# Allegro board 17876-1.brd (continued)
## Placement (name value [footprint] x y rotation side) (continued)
NOREF#57  *  [unnamed]  4.72 13.84 180 bottom
NOREF#58  *  [unnamed]  126.58 2.01 180 bottom
NOREF#59  *  [unnamed]  150.69 1.28 180 bottom
NOREF#60  *  [unnamed]  167.46 98.3 180 bottom
PC4301  SC1U50V3KX-1-GP  [C603H36]  27.1 70 270 bottom
PC4302  SCD1U25V2KX-1-DL-GP  [C402H22]  25.91 70.05 90 top
PC4303  SCD01U50V2KX-1GP  [C402H22]  20.9 64.95 90 bottom
PC4304  SCD01U50V2KX-1DLGP  [C402H22]  20.9 60.99 90 bottom
PC4305  SCD01U50V2KX-1GP  [C402H22]  20.9 61.77 90 bottom
PC4306  SC10U25V5KX-DL-GP  [C805H58]  20.52 66.3 90 bottom
PC4401  SC10U25V5KX-DL-GP  [C805H58]  125.28 14.63 0 bottom
PC4402  SC2200P50V2KX-2DLGP  [C402H22]  139.62 37.82 180 bottom
PC4403  SC2200P50V2KX-2DLGP  [C402H22]  140.41 37.82 180 bottom
PC4404  SC1U10V2KX-1DLGP  [C402H22]  21.51 55.15 0 bottom
PC4405  SCD022U16V2KX-3GP  [C402H22]  142.51 36.27 0 bottom
PC4406  SC560P50V2KX-2DLGP  [C402H22]  142.32 34.11 0 bottom
PC4407  SC1KP50V2KX-1DLGP  [C402H22]  134.24 32.51 0 bottom
PC4408  SC1KP50V2KX-1DLGP  [C402H22]  134.24 30.94 180 bottom
PC4409  SC1KP50V2KX-1DLGP  [C402H22]  134.24 33.99 0 bottom
PC4410  SC10U25V5KX-DL-GP  [C805H58]  123.48 14.63 0 bottom
PC4411  SC10U25V5KX-DL-GP  [C805H58]  129.08 10.12 270 bottom
PC4418  SC10U25V5KX-DL-GP  [C805H58]  133.63 20.98 90 bottom
PC4419  SCD01U50V2KX-1DLGP  [C402H22]  135.84 36.86 90 bottom
PC4427  SC10U25V5KX-DL-GP  [C805H58]  133.63 22.89 90 bottom
PC4431  SCD22U25V3KX-DL-GP  [C603H36]  137.16 28.27 0 bottom
PC4433  SCD47U25V3KX-1-DL-GP  [C603H36]  22.15 43.74 0 bottom
PC4435  SC1U50V3KX-1-GP  [C603H36]  140.56 27.08 270 bottom
PC4436  SC10P50V2JN-4DLGP  [C402H22]  140.08 32.77 270 top
PC4438  SC10U25V5KX-DL-GP  [C805H58]  138.81 23.19 270 bottom
PC4445  SC1U10V2KX-1DLGP  [C402H22]  138.58 27.38 270 bottom
PC4446  SC1U10V2KX-1DLGP  [C402H22]  138.43 31.19 270 top
PC4452  SC10U25V5KX-DL-GP  [C805H58]  129.08 11.95 270 bottom
PC4453  SC10U25V5KX-DL-GP  [C805H58]  133.6 28.02 270 bottom
PC4456  SCD1U25V2KX-1-DL-GP  [C402H22]  140.08 21.87 90 top
PC4459  SC10U25V5KX-DL-GP  [C805H58]  138.81 25.1 270 bottom
PC4461  SC2K2P50V2KX-L-GP  [C402H22]  142.24 29.64 270 bottom
PC4462  SC2K2P50V2KX-L-GP  [C402H22]  143.46 30.13 180 bottom
PC4463  SCD1U25V2KX-1-DL-GP  [C402H22]  143.08 28.83 270 bottom
PC4464  SCD1U25V2KX-1-DL-GP  [C402H22]  127.15 15.61 270 bottom
PC4466  SCD1U25V2KX-1-DL-GP  [C402H22]  133.68 36.88 90 bottom
PC4467  SC2K2P50V2KX-L-GP  [C402H22]  134.49 36.1 90 bottom
PC4468  SC2K2P50V2KX-L-GP  [C402H22]  132.94 35.33 270 bottom
PC4471  SCD22U10V2KX-2-GP  [C402H22]  130.87 15.61 270 bottom
PC4501  SCD1U16V2KX-3GP  [C402H22]  12.83 11.23 90 top
PC4502  SC68P50V2JN-1GP  [C402H22]  12.47 14.84 0 top
PC4503  SC4D7U25V5KX-DL-GP  [C805H54]  20.37 25.27 180 bottom
PC4504  SC4D7U25V5KX-DL-GP  [C805H54]  18.57 25.27 180 bottom
PC4505  SCD1U50V3KX-DL-GP  [C603H35]  17.98 28.32 0 bottom
PC4506  SC10U25V5KX-GP  [C805H56]  22.89 12.22 270 bottom
PC4507  SCD1U50V3KX-DL-GP  [C603H35]  17.55 11.56 180 bottom
PC4508  SCD1U50V3KX-DL-GP  [C603H35]  18.8 17.22 0 bottom
PC4509  SC10U25V5KX-DL-GP  [C805H58]  18.03 15.06 90 bottom
PC4510  SC10U25V5KX-DL-GP  [C805H58]  20.45 16.84 0 bottom
PC4511  SCD1U50V3KX-DL-GP  [C603H35]  12.47 16.13 0 bottom
PC4512  SCD1U50V3KX-DL-GP  [C603H35]  19.29 7.96 90 bottom
PC4513  SCD1U16V2KX-3DLGP  [C402H22]  32.65 20.81 270 top
PC4514  SCD1U16V2KX-3DLGP  [C402H22]  32.44 33.22 0 bottom
PC4515  SC18P50V2JN-1-GP  [C402H22]  8.01 15.01 270 bottom
PC4516  SC18P50V2JN-1-GP  [C402H22]  7.99 12.46 270 bottom
PC4517  SC4D7U6D3V3KX-DLGP  [C603H36]  9.39 13.74 0 bottom
PC4518  SC4D7U6D3V3KX-DLGP  [C603H36]  16.23 11.63 180 bottom
PC4601  SCD01U50V2KX-1DLGP  [C402H22]  29.08 53.6 90 bottom
PC4602  SC1KP50V2KX-1DLGP  [C402H22]  28.24 57.81 270 top
PC4603  SC100P50V2JN-3DLGP  [C402H22]  29.97 57.61 270 top
PC4604  SC390P50V2KX-1-GP  [C402H22]  31.11 58.12 180 top
PC4605  SCD1U25V2KX-1-DL-GP  [C402H22]  26.21 57.1 0 top
PC4606  SCD033U25V2KX-1-GP  [C402H22]  24.43 58.93 180 top
PC4607  SCD047U25V2KX-4-GP  [C402H22]  24.62 56.34 0 top
PC4608  SC330P50V2KX-3-DL-GP  [C402H22]  31.11 60.99 0 top
PC4609  SC1KP50V2KX-1DLGP  [C402H22]  25.14 53.93 180 top
PC4610  SC1U10V2KX-1DLGP  [C402H22]  30.96 52.61 180 bottom
PC4611  SC1U10V2KX-1DLGP  [C402H22]  31.39 50.62 90 bottom
PC4612  SC1KP50V2KX-1DLGP  [C402H22]  24.41 49.99 90 top
PC4613  SC1KP50V2KX-1DLGP  [C402H22]  26.4 50.08 0 bottom
PC4614  SC1KP50V2KX-1DLGP  [C402H22]  29.46 40.89 180 top
PC4615  SC100P50V2JN-3DLGP  [C402H22]  32.07 44.17 0 top
PC4616  SC390P50V2KX-1-GP  [C402H22]  32.85 44.17 0 top
PC4617  SC330P50V2KX-3-DL-GP  [C402H22]  32.33 41.43 270 top
PC4618  SCD033U25V2KX-1-GP  [C402H22]  26.57 44.07 90 top
PC4619  SCD047U25V2KX-4-GP  [C402H22]  26.57 44.96 90 top
PC4620  SCD01U50V2KX-1DLGP  [C402H22]  30.89 44.78 180 top
PC4621  SC330P50V2KX-3GP  [C402H22]  29.16 46.1 270 top
PC4622  SCD1U16V2KX-3DLGP  [C402H22]  27.71 41.56 90 top
PC4623  SCD1U25V2KX-1-DL-GP  [C402H22]  27.71 42.32 90 top
PC4701  SC33P50V2JN-3GP  [C402H22]  36.32 41.86 0 top
PC4702  SCD1U25V2KX-1-DL-GP  [C402H22]  37.08 41.86 0 top
PC4703  SCD1U25V2KX-1-DL-GP  [C402H22]  37.85 41.86 0 top
PC4704  SC10U25V5KX-DL-GP  [C805H58]  34.47 40.97 180 bottom
PC4705  SC10U25V5KX-DL-GP  [C805H58]  36.27 40.97 180 bottom
PC4706  SC10U25V5KX-DL-GP  [C805H58]  35.07 46.99 0 bottom
PC4707  SC10U25V5KX-DL-GP  [C805H58]  38.1 40.97 180 bottom
PC4708  SCD22U25V2KX-4-GP  [C402H22]  34.73 49.89 180 top
PC4709  SC33P50V2JN-3GP  [C402H22]  56.9 44 180 bottom
PC4710  SC22U6D3V3MX-1-DL-GP  [C603H40]  56.64 47.07 270 bottom
PC4711  SCD1U25V2KX-1-DL-GP  [C402H22]  34.67 61.04 270 top
PC4712  SC10U25V5KX-DL-GP  [C805H58]  34.39 62.05 90 bottom
PC4713  SC10U25V5KX-DL-GP  [C805H58]  36.2 66.37 0 bottom
PC4714  SC10U25V5KX-DL-GP  [C805H58]  38.1 66.37 0 bottom
PC4715  SC10U25V5KX-DL-GP  [C805H58]  34.39 60.15 90 bottom
PC4716  SCD1U25V2KX-1-DL-GP  [C402H22]  34.67 62.56 270 top
PC4717  SCD22U25V2KX-4-GP  [C402H22]  32.56 56.31 270 top
PC4718  SC33P50V2JN-3GP  [C402H22]  47.5 61.8 90 bottom
PC4719  SC22U6D3V3MX-1-DL-GP  [C603H40]  49 62.97 90 bottom
PC4720  SC33P50V2JN-3GP  [C402H22]  34.67 61.8 270 top
PC4901  SC33P50V2JN-3GP  [C402H22]  62.33 73.81 0 bottom
PC4902  SC1U10V2KX-1DLGP  [C402H22]  63.09 73.53 0 bottom
PC4903  SC1U10V2KX-1DLGP  [C402H22]  54.15 74.73 90 bottom
PC4904  SC10U6D3V3MX-DL-GP  [C603H36]  55.55 75.52 0 bottom
PC4905  SC10U6D3V3MX-DL-GP  [C603H36]  54.46 69.93 0 bottom
PC4906  SC1U10V2KX-1DLGP  [C402H22]  54.79 73.59 0 bottom
PC4907  SCD1U16V2KX-3GP  [C402H22]  51.33 71.96 90 bottom
PC5201  SC4D7U25V5KX-DL-GP  [C805H54]  28.98 79.66 90 bottom
PC5202  SC1U10V2KX-1DLGP  [C402H22]  30.81 80.01 0 bottom
PC5203  SCD1U25V2KX-1-DL-GP  [C402H22]  33.53 73.1 0 top
PC5204  SC10U25V5KX-DL-GP  [C805H58]  38.58 71.17 180 bottom
PC5205  SC10U25V5KX-DL-GP  [C805H58]  36.75 71.17 180 bottom
PC5206  SCD1U25V2KX-1-DL-GP  [C402H22]  35.46 71.73 0 bottom
PC5207  SC22U6D3V3MX-1-DL-GP  [C603H40]  45.47 77.93 0 bottom
PC5208  SC22U6D3V3MX-1-DL-GP  [C603H40]  49.28 77.93 0 bottom
PC5209  SC22U6D3V3MX-1-DL-GP  [C603H40]  48.59 71.25 180 bottom
PC5210  SC22U6D3V3MX-1-DL-GP  [C603H40]  46.79 71.25 180 bottom
PC5211  SC22U6D3V3MX-1-DL-GP  [C603H40]  44.88 71.25 180 bottom
PC5212  SC22U6D3V3MX-1-DL-GP  [C603H40]  47.37 77.93 0 bottom
PC5213  SCD1U25V2KX-1-DL-GP  [C402H22]  30.17 71.56 270 bottom
PC5214  SC1KP50V2KX-1GP  [C402H22]  34.92 76.28 180 top
PC5301  SC4D7U25V5KX-DL-GP  [C805H54]  132.74 46.74 0 bottom
PC5302  SC1U10V2KX-1DLGP  [C402H22]  132.01 43.45 180 bottom
PC5303  SCD1U25V2KX-1-DL-GP  [C402H22]  144.63 50.57 270 bottom
PC5304  SC10U25V5KX-DL-GP  [C805H58]  141.22 52.43 0 bottom
PC5305  SC10U25V5KX-DL-GP  [C805H58]  142.98 49.51 180 bottom
PC5306  SCD1U25V2KX-1-DL-GP  [C402H22]  141.96 47.3 90 bottom
PC5307  SC1U10V2KX-1DLGP  [C402H22]  141.94 45.26 270 bottom
PC5308  SC22U6D3V3MX-1-DL-GP  [C603H40]  139.01 58.9 270 bottom
PC5309  SC22U6D3V3MX-1-DL-GP  [C603H40]  134.37 61.8 0 bottom
PC5310  SC22U6D3V3MX-1-DL-GP  [C603H40]  136.27 61.8 0 bottom
PC5311  SC22U6D3V3MX-1-DL-GP  [C603H40]  138.05 61.8 0 bottom
PC5312  SC10U6D3V3MX-GP  [C603H38]  141.3 41.86 270 bottom
PC5313  SC10U6D3V3MX-DL-GP  [C603H36]  141.3 43.13 270 bottom
PC5314  SCD1U25V2KX-1-DL-GP  [C402H22]  139.63 40.75 180 bottom
PC5315  SC10U6D3V3MX-DL-GP  [C603H36]  116.59 94.82 0 bottom
PC5316  SC1U10V2KX-1DLGP  [C402H22]  114.88 96.52 180 bottom
PC5317  SCD1U25V2KX-GP  [C402H22]  116.1 98.12 0 bottom
PC5318  SC10U6D3V3MX-DL-GP  [C603H36]  125.68 96.45 270 bottom
PC5319  SC100P50V2JN-3GP  [C402H22]  124.89 97.94 0 bottom
PC5320  SCD1U25V2KX-GP  [C402H22]  116.87 99.14 180 bottom
PC5321  SC1KP50V2KX-1GP  [C402H22]  134.29 49.38 0 top
PC5401  SC22P50V2JN-4DLGP  [C402H22]  106.35 99.26 180 bottom
PC5405  SC10U6D3V3MX-DL-GP  [C603H36]  108.69 95.45 180 bottom
PC5406  SC10U6D3V3MX-DL-GP  [C603H36]  110.01 95.48 180 bottom
PC5407  SC22U6D3V3MX-1-DL-GP  [C603H40]  101.04 93.12 180 bottom
PC5408  SC22U6D3V3MX-1-DL-GP  [C603H40]  99.24 93.12 180 bottom
PC5410  SCD1U25V2KX-GP  [C402H22]  99.42 95.66 90 bottom
PC5411  SCD1U16V2KX-3GP  [C402H22]  104.29 97.99 0 bottom
PC5412  SC680P50V2KX-2GP  [C402H22]  103.38 99.26 90 bottom
PC5418  SC1U10V2KX-1GP  [C402H22]  71.25 25.6 90 bottom
PC5419  SC1U10V2KX-1DLGP  [C402H22]  68.3 23.29 90 bottom
PC5420  SC1U10V2KX-1DLGP  [C402H22]  68.3 24.08 90 bottom
PC6301  SC22U6D3V3MX-1-DL-GP  [C603H40]  41.5 90.1 180 bottom
PC6302  SC10U6D3V3MX-DL-GP  [C603H36]  36.37 85.09 0 bottom
PC6303  SC22P50V2JN-4DLGP  [C402H22]  42.04 86.64 180 bottom
PC6304  SC22U6D3V3MX-1-DL-GP  [C603H40]  42.8 88.95 180 bottom
PC6305  SC1U10V2KX-1DLGP  [C402H22]  37.44 84.74 0 bottom
PD4301  P6SMB27A-GP  [DO214AAAKH97]  21.82 71.58 270 bottom
PD4302  SMF18A-GP  [SOD123AK-2H43]  128.62 14.06 90 bottom
PD4303  LBAV99LT1G-1-GP  [SOT23-2D4-312H44]  9.88 65.89 270 bottom
PD4304  AZ4024-02S-R7G-GP  [SOT23-2D4-312H46]  18.26 76.27 180 bottom
PD4404  L1SS355T1G-GP  [SOD323AKH44]  32.68 57.6 270 bottom
PD4410  BAT54C-12-GP  [SOT-23-9H44]  133.48 25.48 0 bottom
PD5201  AZ4024-01L-R7G-GP  [SOD323AKH40]  40.41 70.97 0 bottom
PD5301  AZ4024-01L-R7G-GP  [SOD323AKH40]  141.15 49.33 0 bottom
PG4407  GAP-CLOSE-PWR-3-GP  [GAP-CLOSE-PWR-3]  28.02 64.64 270 bottom
PG4426  GAP-CLOSE-PWR-3-GP  [GAP-CLOSE-PWR-3]  128.47 4.79 90 bottom
PG4428  GAP-CLOSE-PWR-3-GP  [GAP-CLOSE-PWR-3]  130.05 4.79 90 bottom
PG4429  GAP-CLOSE-PWR-3-GP  [GAP-CLOSE-PWR-3]  26.75 64.64 270 bottom
PG4501  GAP-CLOSE-PWR-6-GP  [GAP-CLOSE-PWR]  33.6 32.03 180 bottom
PG4502  GAP-CLOSE-PWR-6-GP  [GAP-CLOSE-PWR]  35.38 21.16 90 top
PG4503  GAP-CLOSE-PWR-6-GP  [GAP-CLOSE-PWR]  19.25 13.46 90 bottom
PG4504  GAP-CLOSE-PWR-6-GP  [GAP-CLOSE-PWR]  36.14 21.16 90 top
PG4505  GAP-CLOSE-PWR-6-GP  [GAP-CLOSE-PWR]  19.08 28.96 270 bottom
PG4506  GAP-CLOSE-PWR-6-GP  [GAP-CLOSE-PWR]  20.02 13.46 90 bottom
PG4507  GAP-CLOSE-PWR-6-GP  [GAP-CLOSE-PWR]  33.6 31.27 180 bottom
PG4508  GAP-CLOSE-PWR-6-GP  [GAP-CLOSE-PWR]  19.84 28.96 270 bottom
PG4509  GAP-CLOSE-PWR-6-GP  [GAP-CLOSE-PWR]  33.86 21.16 90 top
PG4510  GAP-CLOSE-PWR-6-GP  [GAP-CLOSE-PWR]  20.78 13.46 90 bottom
PG4511  GAP-CLOSE-PWR-6-GP  [GAP-CLOSE-PWR]  36.42 21.16 90 bottom
PG4512  GAP-CLOSE-PWR-6-GP  [GAP-CLOSE-PWR]  33.6 30.51 180 bottom
PG4513  GAP-CLOSE-PWR-6-GP  [GAP-CLOSE-PWR]  20.6 28.96 270 bottom
PG4514  GAP-CLOSE-PWR-6-GP  [GAP-CLOSE-PWR]  18.49 13.46 90 bottom
PG4515  GAP-CLOSE-PWR-6-GP  [GAP-CLOSE-PWR]  33.6 29.75 180 bottom
PG4516  GAP-CLOSE-PWR-6-GP  [GAP-CLOSE-PWR]  34.14 21.16 90 bottom
PG4517  GAP-CLOSE-PWR-6-GP  [GAP-CLOSE-PWR]  33.6 28.98 180 bottom
PG4518  GAP-CLOSE-PWR-6-GP  [GAP-CLOSE-PWR]  34.62 21.16 90 top
PG4519  GAP-CLOSE-PWR-6-GP  [GAP-CLOSE-PWR]  34.9 21.16 90 bottom
PG4520  GAP-CLOSE-PWR-6-GP  [GAP-CLOSE-PWR]  33.6 32.79 180 bottom
PG4521  GAP-CLOSE-PWR-6-GP  [GAP-CLOSE-PWR]  35.66 21.16 90 bottom
PG4522  GAP-CLOSE-PWR-6-GP  [GAP-CLOSE-PWR]  31.6 33.25 90 bottom
PG4523  GAP-CLOSE-PWR-6-GP  [GAP-CLOSE-PWR]  37.06 21.16 90 top
PG4524  GAP-CLOSE-PWR-3-GP  [GAP-CLOSE-PWR-3]  8.03 14.15 0 bottom
PG4525  GAP-CLOSE-PWR-3-GP  [GAP-CLOSE-PWR-3]  16.38 12.3 0 top
PG4601  GAP-CLOSE-PWR-6-GP  [GAP-CLOSE-PWR]  28.22 54.64 180 bottom
PG4602  GAP-CLOSE-PWR-3-GP  [GAP-CLOSE-PWR-3]  32.54 57.22 0 top
PG4603  GAP-CLOSE-PWR-3-GP  [GAP-CLOSE-PWR-3]  24.38 52.71 0 top
PG4604  GAP-CLOSE-PWR-3-GP  [GAP-CLOSE-PWR-3]  24.38 51.77 0 top
PG4605  GAP-CLOSE-PWR-3-GP  [GAP-CLOSE-PWR-3]  24.38 50.83 0 top
PG4606  GAP-CLOSE-PWR-3-GP  [GAP-CLOSE-PWR-3]  24.28 49.13 0 top
PG4607  GAP-CLOSE-PWR-3-GP  [GAP-CLOSE-PWR-3]  24.46 48.08 0 top
PG4608  GAP-CLOSE-PWR-3-GP  [GAP-CLOSE-PWR-3]  35.19 46.86 0 top
PG4609  GAP-CLOSE-PWR-6-GP  [GAP-CLOSE-PWR]  29.97 44.76 270 top
PG4610  GAP-CLOSE-PWR-6-GP  [GAP-CLOSE-PWR]  29.03 44.78 270 top
PG4611  GAP-CLOSE-PWR-6-GP  [GAP-CLOSE-PWR]  30.61 46 0 top
PG4701  GAP-CLOSE-PWR-6-GP  [GAP-CLOSE-PWR]  33.38 42.88 0 bottom
PG4702  GAP-CLOSE-PWR-6-GP  [GAP-CLOSE-PWR]  33.38 45.16 0 bottom
PG4703  GAP-CLOSE-PWR-6-GP  [GAP-CLOSE-PWR]  33.38 43.64 0 bottom
PG4704  GAP-CLOSE-PWR-6-GP  [GAP-CLOSE-PWR]  33.38 45.92 0 bottom
PG4705  GAP-CLOSE-PWR-6-GP  [GAP-CLOSE-PWR]  33.38 44.4 0 bottom
PG4706  GAP-CLOSE-PWR-6-GP  [GAP-CLOSE-PWR]  44.81 48.5 180 bottom
PG4707  GAP-CLOSE-PWR-6-GP  [GAP-CLOSE-PWR]  47.07 48.53 0 bottom
PG4708  GAP-CLOSE-PWR-6-GP  [GAP-CLOSE-PWR]  34.58 64.34 0 bottom
PG4709  GAP-CLOSE-PWR-6-GP  [GAP-CLOSE-PWR]  34.58 65.1 0 bottom
PG4710  GAP-CLOSE-PWR-6-GP  [GAP-CLOSE-PWR]  34.58 65.87 0 bottom
PG4711  GAP-CLOSE-PWR-6-GP  [GAP-CLOSE-PWR]  34.58 63.58 0 bottom
PG4712  GAP-CLOSE-PWR-6-GP  [GAP-CLOSE-PWR]  44.7 57.98 180 bottom
PG4713  GAP-CLOSE-PWR-6-GP  [GAP-CLOSE-PWR]  46.99 57.99 0 bottom
PG4901  GAP-CLOSE-PWR-6-GP  [GAP-CLOSE-PWR]  55.78 68.2 0 bottom
PG4902  GAP-CLOSE-PWR-6-GP  [GAP-CLOSE-PWR]  53.37 69.45 90 bottom
PG4903  GAP-CLOSE-PWR-3-GP  [GAP-CLOSE-PWR-3]  52.55 75.85 270 bottom
PG5201  GAP-CLOSE-PWR-3-GP  [GAP-CLOSE-PWR-3]  42.55 70.84 90 bottom
PG5202  GAP-CLOSE-PWR-3-GP  [GAP-CLOSE-PWR-3]  41.78 70.84 90 bottom
PG5203  GAP-CLOSE-PWR-3-GP  [GAP-CLOSE-PWR-3]  43.31 70.84 90 bottom
PG5204  GAP-CLOSE-PWR-3-GP  [GAP-CLOSE-PWR-3]  50.06 74.45 0 top
PG5205  GAP-CLOSE-PWR-3-GP  [GAP-CLOSE-PWR-3]  50.06 73.69 0 top
PG5206  GAP-CLOSE-PWR-3-GP  [GAP-CLOSE-PWR-3]  50.06 72.93 0 top
PG5207  GAP-CLOSE-PWR-3-GP  [GAP-CLOSE-PWR-3]  50.04 73.71 0 bottom
PG5208  GAP-CLOSE-PWR-3-GP  [GAP-CLOSE-PWR-3]  50.04 74.4 0 bottom
PG5209  GAP-CLOSE-PWR-3-GP  [GAP-CLOSE-PWR-3]  50.04 75.92 0 bottom
PG5210  GAP-CLOSE-PWR-3-GP  [GAP-CLOSE-PWR-3]  50.04 75.16 0 bottom
PG5211  GAP-CLOSE-PWR-3-GP  [GAP-CLOSE-PWR-3]  50.06 75.21 0 top
PG5212  GAP-CLOSE-PWR-6-GP  [GAP-CLOSE-PWR]  48.87 72.52 90 top
PG5301  GAP-CLOSE-PWR-3-GP  [GAP-CLOSE-PWR-3]  143.38 51.69 270 bottom
PG5302  GAP-CLOSE-PWR-3-GP  [GAP-CLOSE-PWR-3]  133.78 57.61 180 top
PG5303  GAP-CLOSE-PWR-3-GP  [GAP-CLOSE-PWR-3]  144.15 51.69 270 bottom
PG5304  GAP-CLOSE-PWR-3-GP  [GAP-CLOSE-PWR-3]  133.78 58.37 180 top
PG5305  GAP-CLOSE-PWR-3-GP  [GAP-CLOSE-PWR-3]  142.62 51.69 270 bottom
PG5306  GAP-CLOSE-PWR-3-GP  [GAP-CLOSE-PWR-3]  133.78 56.08 180 top
PG5307  GAP-CLOSE-PWR-3-GP  [GAP-CLOSE-PWR-3]  133.78 61.42 180 top
PG5308  GAP-CLOSE-PWR-3-GP  [GAP-CLOSE-PWR-3]  133.78 59.89 180 top
PG5309  GAP-CLOSE-PWR-3-GP  [GAP-CLOSE-PWR-3]  133.78 60.66 180 top
PG5310  GAP-CLOSE-PWR-3-GP  [GAP-CLOSE-PWR-3]  133.78 59.13 180 top
PG5311  GAP-CLOSE-PWR-3-GP  [GAP-CLOSE-PWR-3]  133.78 56.85 180 top
PG5312  GAP-CLOSE-PWR-3-GP  [GAP-CLOSE-PWR-3]  141.91 44.4 180 bottom
PG5313  GAP-CLOSE-PWR-6-GP  [GAP-CLOSE-PWR]  134.98 62.26 270 top
PG5314  GAP-CLOSE-PWR-3-GP  [GAP-CLOSE-PWR-3]  141.35 40.48 90 bottom
PG5315  GAP-CLOSE-PWR-3-GP  [GAP-CLOSE-PWR-3]  140.59 40.48 90 bottom
PG5401  GAP-CLOSE-PWR-3-GP  [GAP-CLOSE-PWR-3]  99.47 99.04 180 bottom
PG5402  GAP-CLOSE-PWR-3-GP  [GAP-CLOSE-PWR-3]  111.4 96.72 180 bottom
PG5403  GAP-CLOSE-PWR-3-GP  [GAP-CLOSE-PWR-3]  111.4 95.71 180 bottom
PG5404  GAP-CLOSE-PWR-3-GP  [GAP-CLOSE-PWR-3]  99.44 97.33 0 bottom
PG5405  GAP-CLOSE-PWR-3-GP  [GAP-CLOSE-PWR-3]  99.44 96.57 0 bottom
PG5406  GAP-CLOSE-PWR-3-GP  [GAP-CLOSE-PWR-3]  99.44 98.1 0 bottom
PG5411  GAP-CLOSE-PWR-3-GP  [GAP-CLOSE-PWR-3]  68.3 22.43 180 bottom
PL4401  COIL-4D7UH-33-GP  [L7066-1830-UH119]  138.38 14.15 180 bottom
PL4501  IND-2D2UH-46-GP-U1  [L7066-1830-UH119]  28.88 24.84 180 bottom
PL4502  IND-2D2UH-46-GP-U1  [L7066-1830-UH119]  29.51 17.17 270 bottom
PL4701  COIL-D15UH-7-GP  [L7366-1930H119]  45.97 48.46 270 bottom
PL4702  COIL-D15UH-7-GP  [L7366-1930H119]  45.85 57.86 270 bottom
PL5201  COIL-1UH-34-GP-U1  [L7066-1830-UH119]  40.39 76.28 270 bottom
PL5301  COIL-1UH-34-GP-U1  [L7066-1830-UH119]  136.65 53.8 0 bottom
PL5401  IND-1UH-300-GP  [L2520-D620H48]  102.92 95.94 90 bottom
PL6301  IND-2D2UH-338-GP  [L2520-D620H48]  39.6 89.64 0 bottom
PQ4301  DMG301NU-7-GP  [SOT23DGS2D4H48]  17.04 72.95 90 bottom
PQ4302  LMBT3904LT1G-GP  [SOT23CBE2D4H44]  15.21 69.95 180 bottom
PQ4304  LTC024EUB-FS8-GP  [SC70-2D2-312H44]  13.03 65.64 90 bottom
PQ4305  LTA024EUB-FS8-GP  [SC70-2D2-312H44]  27.41 66.83 90 bottom
PQ4309  2N7002K-2-GP  [SOT23DGS2D4H44]  16.28 66.8 180 bottom
PQ4401  AON7403-GP-U  [PPAK-8P-3232H36]  132.94 10.62 0 bottom
PQ4402  2N7002K-2-GP  [SOT23DGS2D4H44]  22.66 47.4 180 bottom
PQ4405  2N7002KDW-1-GP  [SOT-363H44]  23.98 56.97 180 bottom
PQ4408  AON7403-GP-U  [PPAK-8P-3232H36]  23.24 62.05 270 bottom
PQ4412  2N7002K-2-GP  [SOT23DGS2D4H44]  133.22 16.64 90 bottom
PQ4413  LMBT3906LT1G-1-GP  [SOT23CBE2D4H44]  27.64 58.6 270 bottom
PQ4414  2N7002KDW-1-GP  [SOT-363H44]  23.67 53.7 270 bottom
PQ4415  LTC024EUB-FS8-GP  [SC70-2D2-312H44]  132.97 31.95 180 top
PQ4416  LTA024EUB-FS8-GP  [SC70-2D2-312H44]  133.73 29.03 270 top
PQ4901  2N7002KDW-GP  [SOT-363H44]  51.54 70.11 180 bottom
PR4302  15KR2F-GP  [R402H16]  17.78 70.05 270 bottom
PR4303  10KR2J-3-GP  [R402H16]  13.9 71.05 270 bottom
PR4306  2K2R2J-2-GP  [R402H16]  12.9 67.29 90 bottom
PR4307  33R2J-2-GP  [R402H16]  13.08 68.66 180 bottom
PR4309  240KR3-GP  [R603H22]  27.1 68.73 270 bottom
PR4310  47KR3J-L-GP  [R603H22]  27.1 71.29 90 bottom
PR4311  100KR2J-1-GP  [R402H16]  17.78 70.84 90 bottom
PR4312  1KR2J-1-GP  [R402H16]  14.78 64.77 90 bottom
PR4316  3K3R6J-GP  [R1206H28]  20.04 68.33 90 bottom
PR4401  200KR2F-L-GP  [R402H16]  140.03 31.19 90 top
PR4402  200KR2F-L-GP  [R402H16]  140.06 35.13 90 top
PR4403  95K3R2F-GP  [R402H16]  140.18 31.98 270 top
PR4404  82K5R2F-GP  [R402H16]  140.06 34.32 270 top
PR4405  165KR2F-GP  [R402H16]  141.27 35.79 270 bottom
PR4406  -  [0R0402-PAD]  140.06 33.56 90 top
PR4407  100R2F-L1-GP-U  [R402H14]  143.1 34.22 0 bottom
PR4409  100KR2J-1-GP  [R402H16]  143.23 31.75 0 bottom
PR4410  7K15R2F-L-GP  [R402H16]  141.45 28.86 270 bottom
PR4412  NTC-220K-1-GP-U  [NTC-402H24-U]  142.14 27.54 180 bottom
PR4413  100KR2F-L1-GP  [R402H16]  21.81 53.44 0 bottom
PR4415  -  [0R0402-PAD]  24.1 50.73 180 bottom
PR4416  23K7R2F-GP  [R402H16]  135.89 37.64 90 bottom
PR4417  100KR2J-1-GP  [R402H16]  138.23 28.22 180 top
PR4418  191KR2F-1-GP  [R402H16]  138.99 28.22 0 top
PR4420  10KR2F-2-GP  [R402H16]  21.79 59.26 180 bottom
PR4422  10KR2F-2-GP  [R402H16]  24.77 58.93 270 bottom
PR4426  D01R3721F-GP-U  [R3720H40]  27.38 62.43 270 bottom
PR4428  -  [0R0603-PAD]  135.89 28.27 180 bottom
PR4431  100KR2J-1-GP  [R402H16]  22.58 59.26 180 bottom
PR4432  -  [0R0402-PAD]  30.35 60.3 180 bottom
PR4433  680KR2F-GP  [R402H16]  26.47 57.25 180 bottom
PR4434  300KR2F-L-GP  [R402H16]  22.71 57.03 0 top
PR4435  10KR2F-2-GP  [R402H16]  137.19 37.62 0 top
PR4436  100KR2F-L1-GP  [R402H16]  23.37 59.29 0 bottom
PR4437  2R2F-GP  [R402H16]  136.14 26.62 90 bottom
PR4438  4D7R3F-L-GP  [R603H22]  139.04 28.4 90 bottom
PR4439  100KR2F-L1-GP  [R402H16]  142.75 32.97 270 bottom
PR4440  20KR3J-1-GP  [R603H22]  133.78 19.15 270 bottom
PR4441  100KR2J-1-GP  [R402H16]  25.58 59.72 90 bottom
PR4442  -  [0R0402-PAD]  25.7 57.23 0 bottom
PR4443  D01R3721F-GP-U  [R3720H40]  129.26 7.07 90 bottom
PR4444  1KR2J-1-GP  [R402H16]  128.82 15.61 270 bottom
PR4445  470KR2J-2-GP  [R402H16]  132.11 19.23 0 bottom
PR4446  0R2J-2-GP  [R402H16]  25.53 54.03 0 bottom
PR4447  -  [0R0402-PAD]  24.46 51.97 90 bottom
PR4448  10KR2F-2-GP  [R402H16]  20.73 55.17 0 bottom
PR4449  10KR2F-2-GP  [R402H16]  138 37.59 0 top
PR4450  100KR2F-L1-GP  [R402H16]  22.66 51.34 0 bottom
PR4451  100KR2F-L1-GP  [R402H16]  22.28 56.19 180 bottom
PR4452  150KR2F-L-GP  [R402H16]  135.84 38.43 270 bottom
PR4454  100R5F-2-GP  [R805H24]  132.84 30.43 180 bottom
PR4456  2R2F-GP  [R402H16]  142.91 27.55 0 bottom
PR4457  -  [0R0402-PAD]  143.73 27.55 0 bottom
PR4467  -  [0R0402-PAD]  133.68 37.77 270 bottom
PR4468  2R2F-GP  [R402H16]  132.89 36.1 270 bottom
PR4470  -  [0R0402-PAD]  137.19 37.62 180 bottom
PR4471  -  [0R0402-PAD]  138 37.59 180 bottom
PR4472  100KR2J-1-GP  [R402H16]  21.03 43.44 180 bottom
PR4474  -  [0R0402-PAD]  23.16 55.81 270 top
PR4475  -  [0R0402-PAD]  138.84 37.57 180 bottom
PR4476  -  [0R0402-PAD]  141.21 38.09 180 bottom
PR4477  1KR2F-3-GP  [R402H16]  133.48 34.11 180 bottom
PR4478  100KR2J-1-GP  [R402H16]  21.92 45.39 90 bottom
PR4481  0R2J-2-GP  [R402H16]  133.1 27.26 90 top
PR4502  -  [0R0402-PAD]  12.5 16.41 180 top
PR4503  1D5R3F-GP  [R603H22]  15.24 15.9 180 bottom
PR4504  1D5R3F-GP  [R603H22]  19.28 9.24 270 bottom
PR4505  6K98R2F-GP  [R402H16]  8.94 16.25 180 bottom
PR4506  137KR2F-1-GP  [R402H16]  10.56 16.21 0 bottom
PR4507  95K3R2F-GP  [R402H16]  9.93 11.16 90 bottom
PR4508  10KR2F-2-GP  [R402H16]  9.79 16.21 0 bottom
PR4509  0R2J-2-GP  [R402H16]  8.15 16.27 180 bottom
PR4510  0R2J-2-GP  [R402H16]  6.55 11.99 0 bottom
PR4511  15K4R2F-GP  [R402H16]  7.82 11.66 270 bottom
PR4512  10KR2F-2-GP  [R402H16]  7.9 13.25 90 bottom
PR4513  100KR2J-1-GP  [R402H16]  11.33 16.21 180 bottom
PR4514  -  [0R0402-PAD]  12.62 9.93 0 top
PR4601  10R2F-L-GP  [R402H14]  28.6 60.2 0 top
PR4602  301R2F-GP  [R402H16]  29.87 58.37 270 top
PR4603  390R2F-2GP  [R402H16]  27.03 57.18 0 top
PR4604  68KR2F-GP  [R402H16]  30.86 59.26 270 top
PR4605  2K15R2F-1-GP  [R402H16]  28.24 56.82 270 top
PR4606  2K61R2F-1-GP  [R402H16]  25.4 57.1 0 top
PR4607  2KR2F-3-GP  [R402H16]  30.35 60.53 0 top
PR4608  34KR2F-GP  [R402H16]  29.92 56.82 270 top
PR4609  11KR2F-L-GP  [R402H16]  25.22 58.83 180 top
PR4610  NTC-10K-29-GP-U  [NTC-402H22-U]  46.66 53.52 270 bottom
PR4611  10KR2F-2-GP  [R402H16]  32.39 58.09 270 top
PR4612  11K8R2F-GP  [R402H16]  27.51 53.6 90 bottom
PR4613  NTC-470K-2-GP-U  [NTC-402H22-U]  35.08 56.06 0 bottom
PR4614  27K4R2F-GP  [R402H16]  26.82 52.83 90 bottom
PR4615  133KR2F-GP  [R402H16]  24.37 54.02 180 top
PR4616  1R3J-L1-GP  [R603H22]  31.98 52.2 180 bottom
PR4617  -  [0R0402-PAD]  25.12 46.76 180 top
PR4618  133KR2F-GP  [R402H16]  27.16 50.03 0 bottom
PR4619  300R2J-4-GP  [R402H16]  24.79 49.23 270 bottom
PR4620  10KR2F-2-GP  [R402H16]  34.24 45.98 90 top
PR4621  -  [0R0402-PAD]  25.1 47.98 180 bottom
PR4622  11K8R2F-GP  [R402H16]  28.37 49.86 180 bottom
PR4623  NTC-470K-2-GP-U  [NTC-402H22-U]  35.18 49.31 180 bottom
PR4624  301R2F-GP  [R402H16]  30.73 40.51 270 top
PR4625  2K61R2F-1-GP  [R402H16]  30.73 41.28 270 top
PR4626  27K4R2F-GP  [R402H16]  28.37 48.16 180 bottom
PR4627  68KR2F-GP  [R402H16]  32.38 43.01 270 top
PR4628  2KR2F-3-GP  [R402H16]  32.38 42.19 90 top
PR4629  210KR2F-GP  [R402H16]  32.54 45.3 90 top
PR4630  10KR2F-2-GP  [R402H16]  26.37 46.94 90 top
PR4631  10R2J-2-GP  [R402H14]  30.45 43.64 90 top
PR4632  2K61R2F-1-GP  [R402H16]  26.57 41.81 0 top
PR4633  11KR2F-L-GP  [R402H16]  26.47 43.31 90 top
PR4634  10R2J-2-GP  [R402H14]  28.75 43.64 90 top
PR4635  NTC-10K-29-GP-U  [NTC-402H22-U]  46.66 52.73 270 bottom
PR4636  487R2F-GP  [R402H16]  28.02 45.87 0 top
PR4701  2D2R3-1-U-GP  [R603H22]  34.73 48.51 90 top
PR4702  3K65R2F-1-GP  [R402H16]  25.81 41.81 0 top
PR4703  1R2F-GP  [R402H16]  27.84 40.79 90 top
PR4704  2D2R3-1-U-GP  [R603H22]  33.99 55.55 180 top
PR4705  3K65R2F-1-GP  [R402H16]  26.47 59.18 90 top
PR4706  1R2F-GP  [R402H16]  26.46 58.42 90 top
PR4901  10KR2F-2-GP  [R402H16]  49.89 69.5 180 bottom
PR4902  3K9R2F-GP  [R402H16]  53.21 71.91 0 bottom
PR4903  3KR2F-GP  [R402H16]  54 73.48 0 bottom
PR5201  10R2F-L-GP  [R402H14]  30.36 78.36 90 bottom
PR5202  8K2R2F-1-GP  [R402H16]  32.99 80.34 270 bottom
PR5203  100KR2J-1-GP  [R402H16]  28.42 77.55 270 bottom
PR5204  -  [0R0402-PAD]  28.42 78.31 270 bottom
PR5205  510KR2F-GP  [R402H16]  28.7 76.66 270 bottom
PR5206  0R2J-2-GP  [R402H16]  28.7 75.9 270 bottom
PR5207  2K67R2F-2-GP  [R402H16]  28.78 73.15 0 bottom
PR5208  10KR2F-2-GP  [R402H16]  28.7 74.37 90 bottom
PR5209  -  [0R0402-PAD]  28.7 75.13 270 bottom
PR5210  2R3F-GP  [R603H22]  34.42 69.75 180 bottom
PR5211  2D2R5F-2-GP  [R805H24]  36.83 76.28 270 top
PR5301  10R2F-L-GP  [R402H14]  132.8 44.4 0 bottom
PR5302  6K49R2F-1-GP  [R402H16]  133.56 44.39 0 bottom
PR5303  100KR2J-1-GP  [R402H16]  132.12 40.74 0 bottom
PR5304  510KR2F-GP  [R402H16]  134.32 40.78 0 bottom
PR5306  0R2J-2-GP  [R402H16]  135.09 40.78 0 bottom
PR5307  -  [0R0402-PAD]  136.63 40.69 0 bottom
PR5308  6K04R2F-GP  [R402H16]  137.86 41.15 90 bottom
PR5309  10KR2F-2-GP  [R402H16]  137.86 40.36 270 bottom
PR5310  5D1R3J-GP  [R603H22]  113.21 97.89 180 bottom
PR5311  -  [0R0805-PAD]  114.45 94.41 90 bottom
PR5312  10KR2J-3-GP  [R402H16]  114.86 97.69 270 bottom
PR5313  -  [0R0805-PAD]  125.35 94.36 180 bottom
PR5314  10KR2J-3-GP  [R402H16]  115.65 99.49 270 bottom
PR5315  21K5R2F-GP  [R402H16]  125.67 97.94 0 bottom
PR5316  10KR2F-2-GP  [R402H16]  125.48 99.16 90 bottom
PR5317  2R3F-GP  [R603H22]  142.14 46.28 270 bottom
PR5318  2D2R5F-2-GP  [R805H24]  135.66 50.14 0 top
PR5319  0R2J-2-GP  [R402H16]  135.86 40.7 0 bottom
PR5403  102KR2F-GP  [R402H16]  107.19 99.34 180 bottom
PR5405  51KR2F-L-GP  [R402H16]  108.46 98.83 270 bottom
PR5406  18KR2F-GP  [R402H16]  105 99.26 90 bottom
PR5407  100KR2J-1-GP  [R402H16]  110.19 98.05 90 bottom
PR5409  -  [0R0402-PAD]  103.48 98.05 180 bottom
PR5410  0R2J-2-GP  [R402H16]  68.22 25.66 270 bottom
PR5411  -  [0R0402-PAD]  73.79 18.87 90 bottom
PR5412  -  [0R0402-PAD]  110.19 98.83 90 bottom
PR5413  -  [0R0402-PAD]  68.22 24.87 270 bottom
PR5414  10KR2J-3-GP  [R402H16]  72.14 26.39 270 bottom
PR6301  21KR2F-GP  [R402H16]  41.65 84.95 180 bottom
PR6302  14K3R2F-GP  [R402H16]  42.88 86.67 180 bottom
PR6303  0R3J-L1-GP  [R603H22]  42.24 91.21 180 top
PT4501  ST150U6D3VDM-28-GP  [CT7343H83]  27.08 31.47 90 bottom
PT4502  ST150U6D3VDM-28-GP  [CT7343H83]  37.71 18.01 270 bottom
PT4701  SE330U2VDM-4-GP  [CT7343H83]  52.7 48.08 0 bottom
PT4702  SE330U2VDM-4-GP  [CT7343H83]  51.82 41.48 90 bottom
PT4705  SE330U2VDM-4-GP  [CT7343H83]  52.58 56.47 180 bottom
PT4706  SE330U2VDM-4-GP  [CT7343H83]  52.58 64.59 0 bottom
PT4707  SE33U25VM-11-GP  [CT7343H83]  31.37 67.01 0 bottom
PT4708  SE33U25VM-11-GP  [CT7343H83]  30.18 42.27 180 bottom
PU4301  AON7403-GP-U  [PPAK-8P-3232H36]  23.93 65.46 0 bottom
PU4401  ISL88739HRZ-T-GP-U  [QFN32J4-G2D7H42]  138.05 33.22 180 bottom
PU4411  AON7408-GP  [PPAK-8P-3232H36]  137.03 20.91 180 bottom
PU4412  AON7408-GP  [PPAK-8P-3232H36]  140.84 19.64 0 bottom
PU4501  RT6575DGQW-GP  [QFN20-G1D75H32]  12.7 12.65 270 bottom
PU4502  AON7408-GP  [PPAK-8P-3232H36]  22.71 27.13 270 bottom
PU4503  AON7408-GP  [PPAK-8P-3232H36]  22.78 15.01 270 bottom
PU4504  AON7408-GP  [PPAK-8P-3232H36]  23.98 23.27 90 bottom
PU4505  AON7506-GP  [PPAK-8P-3232H36]  24.03 18.8 90 bottom
PU4601  ISL62771HRTZ-GP-U  [QFN40-G3D5H32]  29.46 51.26 90 top
PU4701  FDMS3600-02-RJK0215-COLAY-GP  [PPAK-8P-G5324H44-COLAY]  38.73 48.59 180 bottom
PU4702  FDMS3600-02-RJK0215-COLAY-GP  [PPAK-8P-G5324H44-COLAY]  42.55 41.86 90 bottom
PU4705  FDMS3600-02-RJK0215-COLAY-GP  [PPAK-8P-G5324H44-COLAY]  38.61 57.61 0 bottom
PU4706  FDMS3600-02-RJK0215-COLAY-GP  [PPAK-8P-G5324H44-COLAY]  42.67 64.59 90 bottom
PU4901  APL5337KAI-TRG-2-GP  [SOIC8-G3530H63]  58.57 71.6 90 bottom
PU5201  G5388K11U-GP  [QFN32J4-G3PH32]  33.02 75.26 270 bottom
PU5301  G5388K11U-GP  [QFN32J4-G3PH32]  137.72 45.95 0 bottom
PU5302  APL5934KAI-TRG-GP-U  [SOIC8-G3530H63]  120.65 96.72 270 bottom
PU5401  RT5797ALGQW-GP  [DFN8-G125065H32]  106.53 96.72 90 bottom
PU5402  RT9078-18GJ5-GP  [SOT-23-5H40]  70.79 23.37 0 bottom
PU6301  SYW232DFC-GP  [DFN8G2-G1711H26]  39.95 86.23 0 bottom
Q801  PJT138KA-GP  [SOT-363H44]  74.42 24.48 180 bottom
Q1701  2N7002KDW-1-GP  [SOT-363H44]  58.04 55.09 180 bottom
Q1702  2N7002KDW-1-GP  [SOT-363H44]  51.74 78.06 180 bottom
Q2401  LMBT3906LT1G-1-GP  [SOT23CBE2D4H44]  37.06 36.73 90 bottom
Q2402  2N7002K-2-GP  [SOT23DGS2D4H44]  65.81 23.14 0 bottom
Q2403  2N7002K-2-GP  [SOT23DGS2D4H44]  40.69 28.14 180 bottom
Q2404  SM2421PSANC-TRG-GP  [SOT23DGS2D4H48]  40.41 22.35 0 bottom
Q2405  2N7002K-2-GP  [SOT23DGS2D4H44]  45.5 16.72 180 bottom
Q2501  BAT54C-12-GP  [SOT-23-9H44]  129.79 95.07 270 bottom
Q2502  2N7002K-2-GP  [SOT23DGS2D4H44]  129.79 98.58 270 bottom
Q2505  2N7002K-2-GP  [SOT23DGS2D4H44]  62.31 24.49 90 bottom
Q2506  SM2421PSANC-TRG-GP  [SOT23DGS2D4H48]  74.57 16.7 90 bottom
Q2507  2N7002K-2-GP  [SOT23DGS2D4H44]  72.1 16.7 90 bottom
Q2601  LMBT3904LT1G-GP  [SOT23CBE2D4H44]  56.72 55.2 0 top
Q2603  2N7002K-2-GP  [SOT23DGS2D4H44]  33.71 36.65 0 bottom
Q2604  2N7002KDW-1-GP  [SOT-363H44]  90.3 15.7 90 bottom
Q2901  2N7002K-2-GP  [SOT23DGS2D4H44]  134.82 95.56 0 bottom
Q4001  2N7002K-2-GP  [SOT23DGS2D4H44]  87.17 77.67 90 bottom
Q5401  2N7002K-2-GP  [SOT23DGS2D4H44]  73.41 21.11 270 bottom
Q5501  LMBT3904LT1G-GP  [SOT23CBE2D4H44]  63.32 75.87 0 bottom
Q5503  LMBT3904LT1G-GP  [SOT23CBE2D4H44]  57.89 76.33 180 bottom
Q5701  2N7002K-2-GP  [SOT23DGS2D4H44]  13.79 82.65 270 bottom
Q5703  DMG301NU-7-GP  [SOT23DGS2D4H48]  13.77 73.2 180 bottom
Q5705  DMG301NU-7-GP  [SOT23DGS2D4H48]  14.81 75.72 0 bottom
Q5707  2N7002K-2-GP  [SOT23DGS2D4H44]  16.38 82.65 270 bottom
Q5708  LMBT3904LT1G-GP  [SOT23CBE2D4H44]  14.35 79 90 bottom
Q6301  DMN5L06K-7-GP  [SOT23DGS2D4H48]  93.22 84.79 90 bottom
Q6501  LDTA144VLT1G-GP  [SOT23CBE2D4H44]  67.89 20.17 90 bottom
Q6502  2N7002K-2-GP  [SOT23DGS2D4H44]  24.28 6.87 0 bottom
Q6503  SM2421PSANC-TRG-GP  [SOT23DGS2D4H48]  42.6 11.65 270 bottom
Q6504  SM2421PSANC-TRG-GP  [SOT23DGS2D4H48]  43.85 7.36 270 bottom
Q6507  2N7002KDW-GP  [SOT-363H44]  45.43 11.27 180 bottom
Q6508  PJT138KA-GP  [SOT-363H44]  40.51 14.33 270 bottom
Q7001  2N7002KDW-1-GP  [SOT-363H44]  92.94 90.02 270 bottom
R301  196R2F-GP  [R402H16]  72.42 50.17 0 top
R302  196R2F-GP  [R402H16]  73.91 48.67 0 top
R501  -  [0R0402-PAD]  95.01 51.1 90 top
R503  39D2R2F-L-GP  [R402H16]  90.02 51.59 90 top
R504  1KR2J-1-GP  [R402H16]  90.02 50.83 90 top
R704  -  [0R0402-PAD]  72.96 62.53 270 top
R801  1KR2J-1-GP  [R402H16]  79.78 31.37 0 bottom
R802  150R2F-1-GP  [R402H16]  77.83 39.65 0 top
R803  2KR2F-3-GP  [R402H16]  77.6 35.46 270 bottom
R808  300R2J-4-GP  [R402H16]  88.14 25.68 270 bottom
R809  1KR2J-1-GP  [R402H16]  82.29 38.15 0 top
R810  -  [0R0402-PAD]  79.98 33.71 0 bottom
R811  1KR2J-1-GP  [R402H16]  77.85 37.42 180 top
R812  1KR2J-1-GP  [R402H16]  80.54 31.4 0 bottom
R813  -  [0R0402-PAD]  78.36 33.73 0 bottom
R816  -  [0R0402-PAD]  88.11 26.57 270 bottom
R818  -  [0R0402-PAD]  82.35 26.16 90 bottom
R820  -  [0R0402-PAD]  79.22 33.71 0 bottom
R821  -  [0R0402-PAD]  89.56 24.59 90 bottom
R822  1KR2J-1-GP  [R402H16]  81.45 38.15 180 top
R823  -  [0R0402-PAD]  84.1 26.16 270 bottom
R1201  -  [0R0402-PAD]  126.75 64.97 90 top
R1202  -  [0R0402-PAD]  121.87 55.91 90 top
R1203  1KR2F-3-GP  [R402H16]  132.38 62.21 0 top
R1204  1KR2F-3-GP  [R402H16]  131.62 63.6 180 top
R1205  0R2J-2-GP  [R402H16]  128.45 66.68 270 top
R1206  1KR2J-1-GP  [R402H16]  129.41 49.25 0 top
R1207  0R2J-2-GP  [R402H16]  125 85.3 90 top
R1208  -  [0R0402-PAD]  126.85 86.72 90 top
R1209  0R2J-2-GP  [R402H16]  129.39 84.28 180 top
R1210  -  [0R0402-PAD]  129.39 85.96 0 top
R1211  0R2J-2-GP  [R402H16]  132.41 63.91 180 top
R1601  1KR2F-3-GP  [R402H16]  72.31 60.91 0 top
R1602  1KR2F-3-GP  [R402H16]  74.42 59.08 270 top
R1603  11K8R2F-GP  [R402H16]  69.65 57.05 270 top
R1607  -  [0R0402-PAD]  63.78 44.73 0 bottom
R1608  -  [0R0402-PAD]  64.56 44.74 0 bottom
R1609  1KR2F-3-GP  [R402H16]  71.75 47.55 0 top
R1610  1KR2F-3-GP  [R402H16]  72.92 54.28 180 top
R1611  -  [0R0402-PAD]  82.5 68.33 180 bottom
R1612  0R2J-2-GP  [R402H16]  80.52 67.06 90 bottom
R1613  10KR2J-3-GP  [R402H16]  86.03 62.31 270 top
R1614  10KR2J-3-GP  [R402H16]  61.29 47.5 90 bottom
R1615  10KR2J-3-GP  [R402H16]  76.45 67.72 180 bottom
R1616  10KR2J-3-GP  [R402H16]  79.17 70.94 0 bottom
R1617  -  [0R0402-PAD]  74.93 68.56 0 bottom
R1618  -  [0R0402-PAD]  81.71 68.33 180 bottom
R1619  -  [0R0402-PAD]  77.24 67.72 0 bottom
R1620  10KR2J-3-GP  [R402H16]  78.36 67.74 180 bottom
R1621  10KR2J-3-GP  [R402H16]  75.69 67.72 180 bottom
R1624  1MR2J-1-GP  [R402H16]  64.34 42.32 180 bottom
R1625  -  [0R0402-PAD]  64.35 40.64 0 bottom
R1629  33R2J-2-GP  [R402H16]  84.81 70.46 180 bottom
R1630  -  [0R0402-PAD]  84.45 67.06 180 bottom
R1631  -  [0R0402-PAD]  82.91 66.07 180 bottom
R1632  -  [0R0402-PAD]  59.89 48.21 180 bottom
R1633  -  [0R0402-PAD]  85.6 69.55 0 bottom
R1634  -  [0R0402-PAD]  70.48 50.9 180 top
R1635  0R2J-2-GP  [R402H16]  84.05 70.44 180 bottom
R1636  10KR2J-3-GP  [R402H16]  85.57 66.91 180 bottom
R1702  10KR2J-3-GP  [R402H16]  61.24 49.86 270 bottom
R1703  10KR2J-3-GP  [R402H16]  63.8 53.09 90 top
R1707  10KR2J-3-GP  [R402H16]  62.31 59.59 90 top
R1708  10KR2J-3-GP  [R402H16]  63.93 49.95 90 top
R1709  10KR2J-3-GP  [R402H16]  60.33 56.57 90 bottom
R1710  10KR2J-3-GP  [R402H16]  63.63 54.76 90 top
R1711  1KR2J-1-GP  [R402H16]  59.44 50.75 270 bottom
R1713  10KR2J-3-GP  [R402H16]  87.68 75.03 180 bottom
R1715  10KR2J-3-GP  [R402H16]  86.89 75.03 180 bottom
R1717  10KR2J-3-GP  [R402H16]  63.68 57.38 90 bottom
R1718  10KR2J-3-GP  [R402H16]  61.39 51.67 270 bottom
R1719  100KR2J-1-GP  [R402H16]  56.72 57.1 270 bottom
R1721  15KR2J-1-GP  [R402H16]  64.03 51.18 270 bottom
R1723  10KR2J-3-GP  [R402H16]  69.01 65.05 270 bottom
R1724  10KR2J-3-GP  [R402H16]  70.79 65.1 90 bottom
R1729  33R2J-2-GP  [R402H16]  71.24 53.44 270 top
R1730  -  [0R0402-PAD]  63.55 50.24 90 bottom
R1731  -  [0R0402-PAD]  61.39 50.85 270 bottom
R1733  10KR2J-3-GP  [R402H16]  61.24 49.07 270 bottom
R1734  -  [0R0402-PAD]  62 57.38 270 bottom
R1735  10KR2J-3-GP  [R402H16]  63.93 50.74 90 top
R1737  -  [0R0402-PAD]  60.33 57.35 90 bottom
R1738  10KR2J-3-GP  [R402H16]  62.71 56.57 270 bottom
R1745  20MR3-GP  [R603H22]  64.44 64.42 180 bottom
R1746  20KR2J-L2-GP  [R402H16]  58.57 56.95 90 bottom
R1747  100KR2J-1-GP  [R402H16]  58.55 53.16 90 bottom
R1748  1KR2J-1-GP  [R402H16]  56.69 57.91 90 bottom
R1756  0R2J-2-GP  [R402H16]  83.69 66.07 180 bottom
R1757  10KR2J-3-GP  [R402H16]  63.4 48.8 270 bottom
R1758  100KR2J-1-GP  [R402H16]  91.04 88.77 0 bottom
R1759  10KR2J-3-GP  [R402H16]  63.8 52.3 90 top
R1760  10KR2J-3-GP  [R402H16]  64.22 51.52 90 top
R1761  10KR2J-3-GP  [R402H16]  86.51 66.45 180 bottom
R2001  10KR2J-3-GP  [R402H16]  62.31 58.78 90 top
R2002  10KR2J-3-GP  [R402H16]  60.6 55.2 0 bottom
R2003  10KR2J-3-GP  [R402H16]  63.25 56.01 0 top
R2004  10KR2J-3-GP  [R402H16]  82.14 72.62 270 bottom
R2005  10KR2J-3-GP  [R402H16]  80.08 68.33 180 bottom
R2006  10KR2J-3-GP  [R402H16]  81.33 71.05 270 bottom
R2007  2KR2J-1-GP  [R402H16]  63.7 57.25 90 top
R2008  2KR2J-1-GP  [R402H16]  61.42 55.2 180 bottom
R2009  2KR2J-1-GP  [R402H16]  64.03 56.01 180 top
R2010  2KR2J-1-GP  [R402H16]  83.03 71.83 270 bottom
R2011  2KR2J-1-GP  [R402H16]  80.89 68.33 0 bottom
R2012  2KR2J-1-GP  [R402H16]  81.33 70.23 90 bottom
R2400  10KR2J-3-GP  [R402H16]  61.09 37.57 90 bottom
R2407  10KR2J-3-GP  [R402H16]  60.5 18.95 90 bottom
R2408  2D2R3-1-U-GP  [R603H22]  62.18 27.41 0 bottom
R2409  -  [0R0603-PAD]  38.71 35.13 0 top
R2410  100KR2J-1-GP  [R402H16]  44.17 30.96 90 top
R2413  -  [0R0402-PAD]  58.93 36.27 90 bottom
R2414  -  [0R0402-PAD]  44.91 28.93 180 top
R2415  -  [0R0402-PAD]  47.19 37.72 0 bottom
R2419  1KR2J-1-GP  [R402H16]  65 34.55 270 bottom
R2420  10KR2J-3-GP  [R402H16]  61.43 36.25 180 bottom
R2421  10KR2J-3-GP  [R402H16]  63.7 33.81 0 bottom
R2422  10KR2J-3-GP  [R402H16]  63.5 30.18 180 bottom
R2423  10KR2J-3-GP  [R402H16]  59.33 23.62 0 top
R2425  -  [0R0402-PAD]  53.64 38.23 0 bottom
R2427  10KR2J-3-GP  [R402H16]  65.52 27.23 90 bottom
R2428  10KR2J-3-GP  [R402H16]  42.98 35.97 270 bottom
R2434  100KR2J-1-GP  [R402H16]  47.96 37.72 180 bottom
R2435  -  [0R0402-PAD]  60.54 36.34 180 bottom
R2436  10KR2J-3-GP  [R402H16]  59.99 34.01 0 bottom
R2437  47KR2J-2-GP  [R402H16]  39.8 34.8 0 top
R2438  100KR2F-L1-GP  [R402H16]  41.38 34.9 180 top
R2440  -  [0R0402-PAD]  61.42 21.7 270 bottom
R2442  100KR2J-1-GP  [R402H16]  63.59 23.17 180 bottom
R2443  1KR2J-1-GP  [R402H16]  56.34 26.57 180 top
R2444  10KR2J-3-GP  [R402H16]  50.88 36.53 180 bottom
R2463  10KR2J-3-GP  [R402H16]  44.73 27.21 90 top
R2465  22K1R2F-L-GP  [R402H16]  49.94 25.91 180 top
R2468  1KR2J-1-GP  [R402H16]  42.16 19.79 180 bottom
R2471  10KR2J-3-GP  [R402H16]  47.97 19.79 270 top
R2472  10KR2J-3-GP  [R402H16]  37.37 34.17 0 bottom
R2473  100KR2J-1-GP  [R402H16]  44.16 18.03 270 bottom
R2474  10KR2J-3-GP  [R402H16]  34.85 33.4 0 bottom
R2475  8K2R2J-3-GP  [R402H16]  57.51 24.56 180 top
R2476  -  [0R0402-PAD]  53.32 32.08 90 top
R2477  -  [0R0402-PAD]  87.32 14.37 90 bottom
R2478  10KR2J-3-GP  [R402H16]  41.58 27.18 180 top
R2486  -  [0R0402-PAD]  40.39 30.1 270 bottom
R2488  -  [0R0402-PAD]  39.98 32.01 270 bottom
R2489  330KR2J-L1-GP  [R402H16]  40.01 32.82 90 bottom
R2490  10KR2J-3-GP  [R402H16]  61.98 29.03 90 bottom
R2491  330KR2J-L1-GP  [R402H16]  40.69 23.78 0 top
R2492  47KR2J-2-GP  [R402H16]  39.75 24.67 0 top
R2493  1KR2J-1-GP  [R402H16]  42.39 24.92 180 top
R2494  -  [0R0402-PAD]  49.88 15.15 90 bottom
R2497  10KR2J-3-GP  [R402H16]  58.66 21.41 270 top
R2498  0R2J-2-GP  [R402H16]  63.65 20.98 180 bottom
R2499  10KR2J-3-GP  [R402H16]  64.9 21.16 90 bottom
R2501  1KR2J-1-GP  [R402H16]  130.07 100.69 270 bottom
R2505  10MR2J-L-GP  [R402H16]  128.5 97.13 0 bottom
R2506  1KR2J-1-GP  [R402H16]  58.04 41.86 270 bottom
R2507  10KR2J-3-GP  [R402H16]  60.2 24.21 0 bottom
R2513  0R2J-2-GP  [R402H16]  128.42 93.7 180 bottom
R2514  0R2J-2-GP  [R402H16]  131.72 94.97 0 bottom
R2515  0R2J-2-GP  [R402H16]  75.76 22.49 0 bottom
R2516  100KR2J-1-GP  [R402H16]  70.14 17.59 0 bottom
R2517  0R2J-2-GP  [R402H16]  71.62 18.82 90 bottom
R2518  100KR2J-1-GP  [R402H16]  75.86 15.3 0 bottom
R2540  4K7R2J-2-GP  [R402H16]  78.77 19.12 180 top
R2601  -  [0R0402-PAD]  94.11 26.24 270 bottom
R2602  0R2J-2-GP  [R402H16]  49.63 36.2 270 bottom
R2603  -  [0R0402-PAD]  49.63 36.98 270 bottom
R2604  NTC-100K-8-GP  [NTC-603H38]  56.77 52.96 90 top
R2605  18K7R2F-GP  [R402H16]  92.13 16.13 0 bottom
R2606  2KR2F-3-GP  [R402H16]  92.42 26.62 270 bottom
R2607  0R2J-2-GP  [R402H16]  32.21 36.96 180 top
R2608  24K9R2F-L-GP  [R402H16]  39.88 33.48 90 top
R2609  -  [0R0402-PAD]  32.21 35.26 0 top
R2612  NTC-100K-8-GP  [NTC-603H38]  94.26 73.15 0 bottom
R2613  -  [0R0402-PAD]  42.57 33.45 180 top
R2614  24K9R2F-L-GP  [R402H16]  39.88 33.63 270 bottom
R2615  2KR2J-1-GP  [R402H16]  50.88 38.2 180 bottom
R2701  -  [0R0805-PAD]  140.49 74.5 180 top
R2702  100KR2J-1-GP  [R402H16]  140.56 94.11 0 top
R2703  -  [0R0603-PAD]  140.74 97.23 270 top
R2704  -  [0R0603-PAD]  138.73 83.62 270 top
R2705  -  [0R0603-PAD]  138.89 97.33 180 top
R2706  -  [0R0603-PAD]  138.73 82.35 270 top
R2707  -  [0R0805-PAD]  138.58 74.5 180 top
R2708  -  [0R0402-PAD]  144.93 97 0 top
R2709  -  [0R0402-PAD]  143.64 81.33 270 top
R2710  100KR2J-1-GP  [R402H16]  151.46 95.33 0 top
R2711  200KR2F-L-GP  [R402H16]  150.6 95.35 0 top
R2712  -  [0R0402-PAD]  153.77 84.81 0 top
R2715  -  [0R0603-PAD]  150.86 86.19 180 top
R2716  100KR2J-1-GP  [R402H16]  153.03 94.72 0 top
R2717  100KR2J-1-GP  [R402H16]  152.53 86.59 90 top
R2718  -  [0R0402-PAD]  152.53 87.38 270 top
R2720  -  [0R0402-PAD]  150.82 88.86 270 top
R2734  -  [0R0402-PAD]  148.21 96.85 0 bottom
R2735  1KR2J-1-GP  [R402H16]  152.63 97.28 180 top
R2741  -  [0R0402-PAD]  148.21 95.07 180 bottom
R2742  -  [0R0603-PAD]  151.35 91.45 0 bottom
R2743  -  [0R0603-PAD]  151.46 78.26 270 top
R2745  -  [0R0603-PAD]  151.46 79.53 270 top
R2747  -  [0R0603-PAD]  151.76 80.98 270 top
R2749  -  [0R0603-PAD]  151.76 82.25 270 top
R2751  -  [0R0805-PAD]  141.3 76.94 90 top
R2752  -  [0R0402-PAD]  144.88 82.46 180 top
R2753  -  [0R0402-PAD]  150.67 91.19 270 top
R2901  HCB1608KF121T30-GP  [L1608-UH38]  89.13 100.2 90 bottom
R2902  HCB1608KF121T30-GP  [L1608-UH38]  89.13 98.93 90 bottom
R2903  HCB1608KF121T30-GP  [L1608-UH38]  89.08 96.88 90 bottom
R2904  HCB1608KF121T30-GP  [L1608-UH38]  89.08 95.61 90 bottom
R2905  100KR2J-1-GP  [R402H16]  137.85 95.61 90 top
R2906  -  [0R0603-PAD]  148.82 96.8 180 top
R2907  -  [0R0603-PAD]  138.66 90.12 180 top
R2908  10R2F-L-GP  [R402H14]  139.67 89.05 0 top
R2909  -  [0R0603-PAD]  137.85 87.73 180 top
R2910  10R2F-L-GP  [R402H14]  139.06 85.68 0 top
R2911  -  [0R0603-PAD]  147.55 96.8 180 top
R2912  4K7R2J-2-GP  [R402H16]  139.73 87.35 0 top
R2914  0R3J-L1-GP  [R603H22]  137.39 94.57 270 top
R2921  1KR2J-1-GP  [R402H16]  139.85 85.68 180 top
R2922  1KR2J-1-GP  [R402H16]  140.44 89.05 180 top
R2928  4K7R2J-2-GP  [R402H16]  140.94 90.35 90 top
R3302  -  [0R0402-PAD]  9.22 36.1 270 bottom
R3303  -  [0R0402-PAD]  12.9 44.2 270 bottom
R3304  6K2R2F-GP  [R402H16]  13.97 36.86 90 bottom
R3307  10KR2J-3-GP  [R402H16]  10.87 43.74 180 bottom
R3309  -  [0R0402-PAD]  11.63 43.74 0 bottom
R3311  -  [0R0402-PAD]  8.1 40.59 270 bottom
R3503  -  [0R0402-PAD]  20.04 44.3 0 bottom
R3504  -  [0R0402-PAD]  19.28 44.3 0 bottom
R3505  -  [0R0402-PAD]  17.75 42.75 0 bottom
R3506  -  [0R0402-PAD]  16.99 42.75 0 bottom
R3605  100KR2J-1-GP  [R402H16]  18.75 61.44 270 bottom
R4001  -  [0R0402-PAD]  35.13 25.43 270 top
R4002  200KR2J-L1-GP  [R402H16]  30.94 36.53 270 top
R4003  1KR2J-1-GP  [R402H16]  30.94 35.74 270 top
R4004  0R2J-2-GP  [R402H16]  41.58 29.77 270 top
R4005  -  [0R0402-PAD]  43.99 14 270 bottom
R4006  10KR2J-3-GP  [R402H16]  43.99 14.77 90 bottom
R4007  -  [0R0402-PAD]  78.82 84.66 180 bottom
R4008  -  [0R0402-PAD]  88.62 76.3 0 bottom
R4009  0R2J-2-GP  [R402H16]  63.35 68.25 0 bottom
R4010  10KR2J-3-GP  [R402H16]  61.14 67.59 270 bottom
R4011  10KR2J-3-GP  [R402H16]  62.59 68.25 0 bottom
R4012  -  [0R0402-PAD]  35.51 26.7 180 top
R4013  10KR2J-3-GP  [R402H16]  87.93 80.09 90 bottom
R4014  1MR2J-1-GP  [R402H16]  40.51 35.94 270 bottom
R4015  0R2J-2-GP  [R402H16]  87.66 85.92 180 bottom
R4016  -  [0R0402-PAD]  86.76 81.98 270 bottom
R4301  -  [0R0402-PAD]  112.39 14.17 90 top
R5501  -  [0R0402-PAD]  55.68 82.02 90 bottom
R5502  -  [0R0402-PAD]  56.03 82.45 0 top
R5503  -  [0R0402-PAD]  66.24 77.09 0 bottom
R5504  33R2J-2-GP  [R402H16]  60.32 82.48 90 top
R5505  100KR2J-1-GP  [R402H16]  58.37 77.47 90 top
R5506  100KR2J-1-GP  [R402H16]  56.92 82.48 180 top
R5507  100KR2J-1-GP  [R402H16]  59.82 80.14 0 top
R5508  100KR2J-1-GP  [R402H16]  65.43 77.12 0 bottom
R5516  2K2R2J-2-GP  [R402H16]  70.64 78.13 180 bottom
R5521  2K2R2J-2-GP  [R402H16]  60.78 76.23 270 bottom
R5522  100KR2J-1-GP  [R402H16]  68.17 74.75 270 bottom
R5524  0R2J-2-GP  [R402H16]  58.39 78.23 90 top
R5526  2K2R2J-2-GP  [R402H16]  60.43 75.47 90 bottom
R5527  10KR2J-3-GP  [R402H16]  60.43 77.07 90 bottom
R5533  0R5J-5-GP  [R805H24]  69.27 80.04 0 bottom
R5534  0R5J-5-GP  [R805H24]  65.89 79.45 0 bottom
R5701  10KR2J-3-GP  [R402H16]  17.73 77.37 270 top
R5702  -  [0R0402-PAD]  16.61 85.94 180 top
R5709  100KR2J-1-GP  [R402H16]  14.41 77.42 270 top
R5710  150KR2F-L-GP  [R402H16]  14.86 85.4 180 top
R5711  200KR2F-L-GP  [R402H16]  14.07 85.4 180 top
R5712  -  [0R0402-PAD]  14.4 76.66 270 top
R5719  100KR2J-1-GP  [R402H16]  13.16 74.51 270 top
R6001  -  [0R0402-PAD]  144.93 19.28 0 bottom
R6002  10KR2J-3-GP  [R402H16]  150.16 52.76 0 bottom
R6003  10KR2J-3-GP  [R402H16]  141.05 55.07 270 bottom
R6004  10KR2J-3-GP  [R402H16]  142.04 55.83 270 bottom
R6005  10KR2J-3-GP  [R402H16]  150.95 52.76 180 bottom
R6006  10KR2J-3-GP  [R402H16]  143.13 65.13 270 top
R6007  10KR2J-3-GP  [R402H16]  143.26 55.27 0 bottom
R6008  10KR2J-3-GP  [R402H16]  142.04 56.59 90 bottom
R6009  10KR2J-3-GP  [R402H16]  142.14 65.89 270 top
R6010  4K7R2J-2-GP  [R402H16]  143.74 53.95 270 bottom
R6011  4K7R2J-2-GP  [R402H16]  141.05 54.28 270 bottom
R6012  4K7R2J-2-GP  [R402H16]  150.8 56.59 180 bottom
R6013  4K7R2J-2-GP  [R402H16]  150.01 56.59 0 bottom
R6014  0R5J-5-GP  [R805H24]  143.81 36.55 180 bottom
R6015  0R5J-5-GP  [R805H24]  145.64 36.55 180 bottom
R6016  0R2J-2-GP  [R402H16]  145.9 41.45 270 top
R6017  0R2J-2-GP  [R402H16]  145.9 42.22 270 top
R6018  0R2J-2-GP  [R402H16]  145.92 43.51 270 top
R6019  0R2J-2-GP  [R402H16]  145.92 44.4 270 top
R6101  -  [0R0402-PAD]  148.79 83.52 90 bottom
R6104  -  [0R0402-PAD]  148.79 82.73 90 bottom
R6105  -  [0R0603-PAD]  149.2 74.47 270 bottom
R6106  0R2J-2-GP  [R402H16]  149.33 75.72 270 bottom
R6107  0R2J-2-GP  [R402H16]  163.25 86.08 90 top
R6108  0R2J-2-GP  [R402H16]  163.25 86.84 90 top
R6109  0R2J-2-GP  [R402H16]  163.32 84.08 90 top
R6110  0R2J-2-GP  [R402H16]  162.13 76.59 270 top
R6111  10KR2J-3-GP  [R402H16]  160.9 77.55 0 top
R6112  10KR2J-3-GP  [R402H16]  162.99 82.31 0 top
R6113  0R2J-2-GP  [R402H16]  163.77 82.31 0 top
R6309  10KR2J-3-GP  [R402H16]  93.14 86.9 270 bottom
R6312  22R2J-2-GP  [R402H16]  83.34 85.8 180 bottom
R6313  4K7R2J-2-GP  [R402H16]  61.01 88.9 90 top
R6324  -  [0R0603-PAD]  90.25 87.29 270 bottom
R6325  -  [0R0603-PAD]  84.18 83.47 90 bottom
R6327  0R2J-2-GP  [R402H16]  94.54 86.39 180 bottom
R6328  0R2J-2-GP  [R402H16]  94.36 82.02 180 bottom
R6343  0R2J-2-GP  [R402H16]  83.34 87.5 0 bottom
R6344  22R2J-2-GP  [R402H16]  59.21 88.65 270 top
R6345  100KR2J-1-GP  [R402H16]  52.8 85.35 0 top
R6346  4K7R2J-2-GP  [R402H16]  57.94 92.76 270 top
R6347  10KR2J-3-GP  [R402H16]  59.82 92.23 270 top
R6348  10KR2J-3-GP  [R402H16]  59.61 86.31 180 top
R6353  1MR2J-1-GP  [R402H16]  47.29 91.87 180 top
R6354  10KR2J-3-GP  [R402H16]  28.42 84.56 180 bottom
R6355  10KR2J-3-GP  [R402H16]  52.68 94.49 180 top
R6356  10KR2J-3-GP  [R402H16]  59.46 95.1 0 top
R6357  10KR2J-3-GP  [R402H16]  53.44 94.49 180 top
R6359  10KR2J-3-GP  [R402H16]  57.45 94.92 270 top
R6360  470KR2J-2-GP  [R402H16]  55.45 95.23 90 top
R6361  470KR2J-2-GP  [R402H16]  54.2 95.12 0 top
R6364  10KR2J-3-GP  [R402H16]  58.67 95.1 0 top
R6365  680R2J-3-GP  [R402H16]  47.29 93.58 180 top
R6501  0R2J-2-GP  [R402H16]  42.56 8.68 0 bottom
R6502  -  [0R0402-PAD]  69.72 19 90 bottom
R6503  1KR2J-1-GP  [R402H16]  70.05 21.01 270 bottom
R6504  4K7R2J-2-GP  [R402H16]  45.73 13.74 180 bottom
R6505  220R2J-L2-GP  [R402H16]  46.52 13.75 180 bottom
R6506  220R2J-L2-GP  [R402H16]  46.29 9.29 90 bottom
R6510  0R2J-2-GP  [R402H16]  25.61 5.56 90 bottom
R6512  2K2R2J-2-GP  [R402H16]  26.39 6.92 180 bottom
R6513  0R2J-2-GP  [R402H16]  41.55 9.09 180 bottom
R6514  -  [0R0402-PAD]  47.38 7.22 180 bottom
R6515  -  [0R0402-PAD]  102.49 14.05 270 bottom
R6516  1KR2J-1-GP  [R402H16]  45.81 7.97 0 bottom
R6518  0R2J-2-GP  [R402H16]  48.17 6.48 0 bottom
R6520  100KR2J-1-GP  [R402H16]  27.18 6.91 180 bottom
R6701  100KR2J-1-GP  [R402H16]  8.74 43.54 270 top
R6801  0R2J-2-GP  [R402H16]  51.59 29.64 180 top
R6802  0R2J-2-GP  [R402H16]  50.8 29.64 180 top
R6803  0R2J-2-GP  [R402H16]  49.99 29.64 180 top
R6804  33R2J-2-GP  [R402H16]  85.75 16.16 90 top
R6901  0R2J-2-GP  [R402H16]  93.8 85.4 90 top
R6902  10KR2J-3-GP  [R402H16]  98.78 85.96 270 top
R6903  0R2J-2-GP  [R402H16]  98.78 85.14 270 top
R6905  10KR2J-3-GP  [R402H16]  98.81 84.28 270 top
R6933  0R2J-2-GP  [R402H16]  96.32 81.81 90 top
R6934  0R2J-2-GP  [R402H16]  94.76 82.04 0 top
R6935  0R2J-2-GP  [R402H16]  100.07 83.22 270 top
R6936  0R2J-2-GP  [R402H16]  96.75 87.33 0 top
R6937  0R2J-2-GP  [R402H16]  93.99 82.04 0 top
R7001  0R2J-2-GP  [R402H16]  91.1 90.47 0 bottom
R7002  100KR2J-1-GP  [R402H16]  94.23 88.22 0 bottom
R7005  10KR2J-3-GP  [R402H16]  96.43 89.95 270 bottom
RN803  SRN1KJ-4-GP  [ARES8-CN24H20]  82.19 31.35 0 bottom
RN804  SRN1KJ-4-GP  [ARES8-CN24H20]  84.73 31.35 180 bottom
RN806  SRN1KJ-7-GP  [SMD-ARES4H18]  85.27 27.94 270 bottom
RN807  SRN1KJ-7-GP  [SMD-ARES4H18]  78.64 31.42 180 bottom
RN808  SRN1KJ-7-GP  [SMD-ARES4H18]  81.03 39.96 0 top
RN809  SRN1KJ-7-GP  [SMD-ARES4H18]  96.01 24.82 180 top
RN810  SRN0J-6-GP  [SMD-ARES4H20]  85.37 39.3 180 top
RN811  SRN4K7J-8-GP  [SMD-ARES4H18]  76.61 39.47 0 top
RN1601  SRN10KJ-5-GP  [ARES2H18]  76.63 25.78 90 bottom
RN1603  SRN0J-6-GP  [SMD-ARES4H20]  76.43 71.32 180 bottom
RN1604  SRN0J-6-GP  [SMD-ARES4H20]  77.95 71.02 180 bottom
RN1605  SRN0J-6-GP  [SMD-ARES4H20]  85.7 75.01 0 bottom
RN1606  SRN0J-6-GP  [SMD-ARES4H20]  84.12 74.98 0 bottom
RN1701  SRN2K2J-1-GP  [ARES2H16]  60.66 53.29 0 bottom
RN1703  SRN2K2J-1-GP  [ARES2H16]  92.58 65.46 270 bottom
RN1704  SRN2K2J-1-GP  [ARES2H16]  42.52 17.8 180 bottom
RN1705  SRN10KJ-5-GP  [ARES2H18]  78.64 74.5 0 bottom
RN1706  SRN100KJ-6-GP  [SMD-ARES4]  53.8 76.13 180 bottom
RN1707  SRN33J-7-GP-U  [ARES8-CN24-UH20]  64.69 73.13 0 bottom
RN1708  SRN15KJ-3-GP  [SMD-ARES4H18]  64.03 52.86 270 bottom
RN1709  SRN1KJ-7-GP  [SMD-ARES4H18]  63.48 70.44 0 bottom
RN1710  SRN10KJ-5-GP  [ARES2H18]  66.65 65.38 90 bottom
RN2401  SRN2K2J-1-GP  [ARES2H16]  42.16 18.32 0 top
RN2403  SRN100KJ-6-GP  [SMD-ARES4]  44.81 17.65 0 top
RN2404  SRN2K2J-1-GP  [ARES2H16]  42.47 22.38 0 top
RN2405  SRN0J-6-GP  [SMD-ARES4H20]  47.9 28.68 180 top
RN2406  SRN0J-6-GP  [SMD-ARES4H20]  46.38 28.68 180 top
RN2407  SRN10KJ-5-GP  [ARES2H18]  55.16 32.08 0 top
RN2601  SRN2K2J-1-GP  [ARES2H16]  87.38 15.53 270 bottom
RN2901  SRN2K2J-1-GP  [ARES2H16]  148.97 94.87 90 top
RN4301  SRN100J-3-GP  [SMD-ARES4H18]  111.96 15.5 270 top
RN4302  SRN100J-3-GP  [SMD-ARES4H18]  111.96 17.05 270 top
RN5502  SRN33J-5-GP-U  [SMD-ARES4H18]  54.86 82.04 180 top
RN5503  SRN100J-3-GP  [SMD-ARES4H18]  58.65 80.09 180 top
